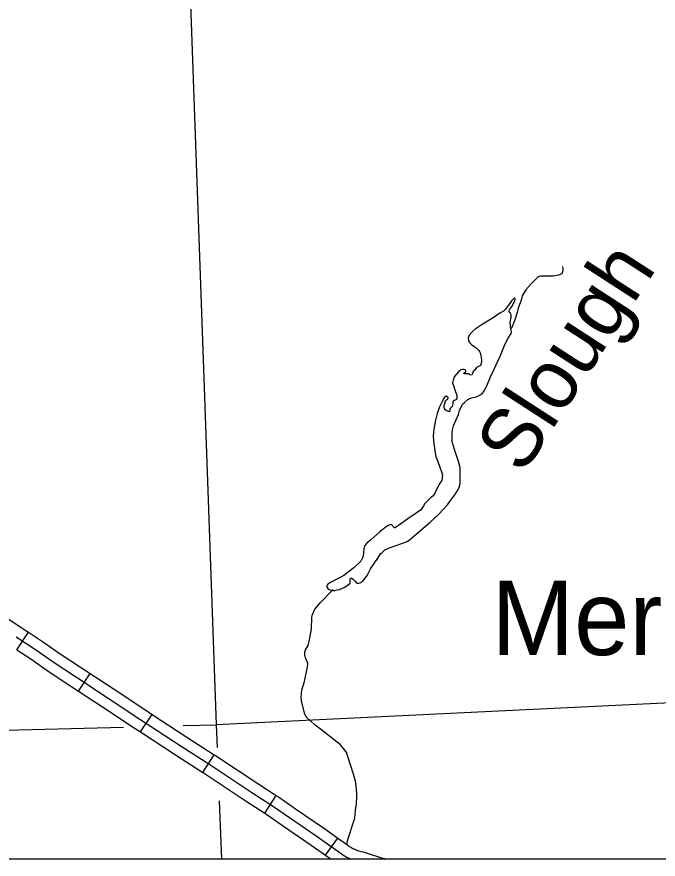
# Model space of a CAD drawing. Extents: x 1720274 to 1751788, y 372074 to 391887.
# Drawn here: x 1734994 to 1735715, y 374371 to 375317 of the extents above; entities that cross this region are included whole.
import ezdxf

# ---------------------------------------------------------------- set-up
doc = ezdxf.new("R2010")
doc.units = 0
for name, color, linetype in [('Level 25', 7, 'Continuous'), ('Level 32', 7, 'Continuous'), ('Level 35', 7, 'Continuous'), ('Level 5', 7, 'Continuous'), ('R_Draft', 7, 'Continuous')]:
    doc.layers.add(name, color=color, linetype=linetype)

msp = doc.modelspace()

# ---------------------------------------------------------------- linework, layer by layer
at = {"layer": 'Level 32'}
for p, q in [((1734993.93, 374606.46), (1735006.85, 374626.33)), ((1735063.16, 374560.09), (1735076.22, 374579.87)), ((1735132.84, 374514.16), (1735145.85, 374533.97)), ((1735202.92, 374468.64), (1735215.69, 374488.61)), ((1735272.54, 374422.84), (1735285.46, 374442.71)), ((1735340.78, 374375.71), (1735354.51, 374395.03))]:
    msp.add_line(p, q, dxfattribs=at)
for points in [[(1734937.32, 374672.25), (1734999.77, 374630.93), (1735006.85, 374626.33)], [(1735006.85, 374626.33), (1735022.85, 374615.93), (1735041.32, 374602.75), (1735066.53, 374586.27), (1735076.22, 374579.87)], [(1734993.27, 374621.02), (1735016.17, 374606.14), (1735034.63, 374592.96), (1735060.02, 374576.37), (1735096.69, 374552.16), (1735133.44, 374527.95), (1735178.48, 374498.35), (1735210.7, 374477.73), (1735258.14, 374446.33), (1735281.3, 374431.28), (1735300.45, 374418.1), (1735331.56, 374396.8), (1735358.44, 374377.71), (1735359.91, 374376.64), (1735361.42, 374375.61), (1735362.96, 374374.64), (1735364.53, 374373.73), (1735366.14, 374372.86), (1735367.77, 374372.06), (1735369.4, 374371.32)], [(1734993.93, 374606.46), (1735009.5, 374596.34), (1735027.95, 374583.18), (1735053.51, 374566.46), (1735063.16, 374560.09)], [(1735076.22, 374579.87), (1735103.21, 374562.05), (1735139.95, 374537.84), (1735145.85, 374533.97)], [(1735063.16, 374560.09), (1735090.16, 374542.26), (1735126.93, 374518.05), (1735132.84, 374514.16)], [(1735145.85, 374533.97), (1735184.93, 374508.29), (1735215.69, 374488.61)], [(1735132.84, 374514.16), (1735172.03, 374488.4), (1735202.92, 374468.64)], [(1735215.69, 374488.6), (1735217.17, 374487.66), (1735264.64, 374456.24), (1735285.46, 374442.71)], [(1735202.92, 374468.64), (1735204.24, 374467.8), (1735251.64, 374436.42), (1735272.54, 374422.84)], [(1735285.46, 374442.71), (1735287.89, 374441.13), (1735307.16, 374427.87), (1735338.34, 374406.52), (1735354.51, 374395.03)], [(1735272.54, 374422.84), (1735274.71, 374421.43), (1735293.74, 374408.33), (1735324.78, 374387.08), (1735340.78, 374375.71)], [(1735354.51, 374395.03), (1735365.36, 374387.33), (1735366.73, 374386.33), (1735367.9, 374385.53), (1735369.1, 374384.78), (1735370.32, 374384.07), (1735371.56, 374383.4), (1735372.83, 374382.77), (1735374.12, 374382.19), (1735375.42, 374381.66), (1735376.75, 374381.17), (1735378.09, 374380.72), (1735379.45, 374380.32), (1735380.81, 374379.97), (1735382.91, 374379.51), (1735404.81, 374372.58), (1735406.93, 374371.88), (1735408.47, 374371.32)], [(1735340.78, 374375.71), (1735346.96, 374371.32)]]:
    msp.add_lwpolyline(points, dxfattribs=at)
at = {"layer": 'Level 35'}
for points in [[(1735607.12, 375036.81), (1735607.45, 375033.83), (1735607.45, 375032.17), (1735607.12, 375031.02), (1735606.79, 375029.86), (1735606.13, 375028.87), (1735605.14, 375028.21), (1735602.66, 375027.38), (1735596.72, 375026.06), (1735594.07, 375025.89), (1735589.12, 375026.06), (1735586.47, 375026.22), (1735584.65, 375026.22), (1735582.42, 375026.01), (1735581.3, 375025.74), (1735580.25, 375025.22), (1735578.93, 375024.43), (1735578.08, 375023.7), (1735571.49, 375017.18), (1735565.97, 375010.59), (1735562.68, 375005.85), (1735561.82, 375003.87), (1735560.57, 374999.13), (1735557.35, 374990.04), (1735556.03, 374985.23), (1735553.2, 374976.01), (1735549.65, 374967.64), (1735548.97, 374966.88)], [(1735551.51, 375000.38), (1735550.11, 374998.77), (1735546.99, 374994.46), (1735542.94, 374989.01), (1735540.73, 374986.81), (1735536.68, 374984.6), (1735529.14, 374979.27), (1735516.97, 374971.96), (1735508.74, 374966.51), (1735505.38, 374963.49), (1735502.6, 374960.13), (1735501.26, 374957.56), (1735501.21, 374956.69), (1735501.16, 374955.88), (1735501.32, 374954.52), (1735501.59, 374953.49), (1735502.46, 374951.76), (1735505.27, 374948.89), (1735509.98, 374945.63), (1735512.04, 374943.68), (1735513.02, 374942.6), (1735513.78, 374941.46), (1735514.43, 374940.1), (1735515.4, 374936.47), (1735515.89, 374932.08), (1735515.89, 374929.75), (1735515.83, 374928.61), (1735515.45, 374926.77), (1735514.75, 374925.68), (1735511.88, 374924.38), (1735510.31, 374923.46), (1735509.5, 374922.48), (1735508.31, 374920.69), (1735507.6, 374920.15), (1735506.63, 374919.12), (1735506.14, 374917.82), (1735505.92, 374916.63), (1735505.65, 374915.82), (1735505.11, 374915.27), (1735504.35, 374915.06), (1735503.43, 374915.17), (1735502.56, 374915.92), (1735501.86, 374916.3), (1735501.1, 374916.52), (1735499.96, 374916.47), (1735499.31, 374916.41), (1735498.12, 374916.41), (1735497.2, 374916.47), (1735496.44, 374916.74), (1735496.33, 374917.17), (1735496.61, 374917.71), (1735497.42, 374917.98), (1735498.45, 374918.53), (1735498.61, 374919.12), (1735498.61, 374919.56), (1735498.18, 374920.32), (1735497.58, 374920.8), (1735495.68, 374921.24), (1735494.44, 374921.24), (1735492.92, 374920.8), (1735490.05, 374918.69), (1735485.39, 374912.94), (1735484.04, 374909.09), (1735483.71, 374907.79), (1735483.61, 374906.06), (1735484.47, 374903.46), (1735486.21, 374898.58), (1735486.86, 374896.3), (1735487.61, 374894.13), (1735488.16, 374892.07), (1735488.26, 374890.01), (1735488.26, 374888.6), (1735487.78, 374887.58), (1735487.23, 374887.09), (1735486.62, 374886.91), (1735485.77, 374886.61), (1735484.8, 374886.31), (1735483.95, 374885.21), (1735483.71, 374882.66), (1735482.92, 374879.86), (1735481.52, 374878.22), (1735480.8, 374877.37), (1735480.49, 374876.16), (1735480.49, 374875.37), (1735480.49, 374874.64), (1735480.25, 374874.27), (1735479.7, 374874.03), (1735478.85, 374874.09), (1735477.64, 374874.52), (1735476.12, 374875.67), (1735474.54, 374876.89), (1735474.3, 374877.56), (1735474.12, 374878.35), (1735474.12, 374879.2), (1735474.18, 374880.47), (1735474.36, 374882.17), (1735475.15, 374884.18), (1735475.39, 374885.58), (1735475.94, 374886.49), (1735476.73, 374887.22), (1735477.7, 374887.95)], [(1735549.8, 374963.52), (1735549.78, 374963.91), (1735549.37, 374965.45), (1735548.97, 374966.88), (1735548.36, 374974.21), (1735549.23, 374979.89), (1735549.3, 374982.45), (1735548.93, 374983.81), (1735548.62, 374984.42), (1735548.19, 374984.79), (1735547.63, 374985.29), (1735547.33, 374985.72), (1735547.14, 374986.15), (1735547.08, 374986.83), (1735547.14, 374987.63), (1735547.94, 374989.17), (1735549.97, 374992), (1735552.62, 374996.81), (1735553.67, 374998.66), (1735553.85, 374999.95), (1735553.85, 375000.51), (1735553.79, 375001), (1735553.54, 375001.18), (1735553.24, 375001.37), (1735552.93, 375001.37), (1735552.56, 375001.25), (1735551.51, 375000.38)], [(1735372.72, 374698.32), (1735361.34, 374689.73), (1735358.13, 374688.03), (1735354.17, 374686.14), (1735346.26, 374681.99), (1735344.66, 374680.78), (1735343.4, 374680.1), (1735342.72, 374679.13), (1735342.43, 374678.54), (1735342.43, 374677.57), (1735342.53, 374676.5), (1735343.4, 374675.33), (1735344.96, 374674.07), (1735346.7, 374673.29), (1735348.06, 374673.2), (1735349.33, 374673.2), (1735351.27, 374673.2), (1735353.99, 374673.78), (1735356.42, 374674.26), (1735362.54, 374676.69), (1735368.27, 374680.88), (1735368.46, 374681.36), (1735368.46, 374682.53), (1735368.46, 374683.5), (1735368.46, 374684.76), (1735368.46, 374685.64), (1735368.56, 374686.32), (1735368.95, 374686.71), (1735369.43, 374686.81), (1735370.21, 374686.81), (1735372.15, 374685.44), (1735373.03, 374684.57), (1735374.58, 374683.01), (1735375.36, 374682.04), (1735376.33, 374681.26), (1735377.1, 374681.07), (1735378.27, 374681.17), (1735379.53, 374681.75), (1735382.35, 374683.31), (1735384.68, 374685.93), (1735387.4, 374689.72), (1735391.38, 374697.3), (1735399.44, 374709.36), (1735402.65, 374714.12), (1735404.4, 374715.87), (1735406.15, 374717.62), (1735407.6, 374718.69), (1735408.57, 374719.28), (1735411.39, 374720.44), (1735424.31, 374725.11), (1735432.47, 374728.03), (1735435.19, 374729.77), (1735437.81, 374732.21), (1735445, 374738.23), (1735458.5, 374749.8), (1735467.87, 374758.56), (1735477.7, 374769.15), (1735481.35, 374774.12), (1735486.04, 374780.59), (1735489.78, 374786.49), (1735490.91, 374789.02), (1735491.94, 374793.15), (1735492.12, 374798.4), (1735492.12, 374804.77), (1735491.94, 374810.77), (1735491.75, 374812.65), (1735490.34, 374817.99), (1735485.57, 374831.39), (1735483.41, 374838.89), (1735483.04, 374840.67), (1735482.95, 374844.89), (1735482.95, 374850.14), (1735483.51, 374853.42), (1735484.63, 374858.11), (1735485.57, 374860.74), (1735490.16, 374870.86), (1735491.47, 374875.08), (1735494.77, 374882.21), (1735496.56, 374884), (1735500.73, 374887.5), (1735503.11, 374888.77), (1735505.12, 374889.59), (1735508.47, 374890.19), (1735510.03, 374890.56), (1735511.97, 374891.38), (1735515.32, 374893.32), (1735517.11, 374894.66), (1735518.3, 374896.15), (1735519.19, 374897.34), (1735522.17, 374903.01), (1735526.27, 374913.07), (1735529.54, 374920.22), (1735537.21, 374936.99), (1735542.58, 374949.96), (1735545.95, 374956.41), (1735549.19, 374961.84), (1735549.76, 374963.12), (1735549.82, 374963.3), (1735549.8, 374963.52)], [(1735477.7, 374887.95), (1735478.43, 374888.67), (1735478.49, 374889.34), (1735478.43, 374889.65), (1735478, 374890.32), (1735477.28, 374890.8), (1735476.73, 374891.04), (1735476.18, 374891.17), (1735475.58, 374891.11), (1735475.09, 374890.86), (1735474.48, 374890.25), (1735473.39, 374888.31), (1735469.02, 374879.26), (1735466.11, 374871.97), (1735464.27, 374864.28), (1735462.38, 374854.16), (1735461.81, 374846.69), (1735462.1, 374841.02), (1735463.42, 374829.95), (1735464.74, 374823.52), (1735468.52, 374813.97), (1735471.83, 374804.04), (1735472.21, 374802.34), (1735472.02, 374800.92), (1735471.83, 374798.65), (1735471.36, 374797.05), (1735469.47, 374793.83), (1735465.78, 374787.21), (1735463.42, 374782.2), (1735461.62, 374779.36), (1735458.6, 374777), (1735453.97, 374772.27), (1735451.89, 374770.38), (1735451.14, 374768.58), (1735449.06, 374765.18), (1735447.64, 374763.38), (1735442.63, 374759.88), (1735433.28, 374753.45), (1735422.7, 374745.98), (1735420.53, 374744.37), (1735418.54, 374743.43), (1735417.79, 374743.52), (1735417.12, 374744.28), (1735416.75, 374744.94), (1735416.27, 374745.79), (1735415.33, 374746.74), (1735414.48, 374746.93), (1735413.06, 374746.83), (1735410.98, 374746.08), (1735407.58, 374743.43), (1735401.72, 374738.89), (1735391.71, 374730), (1735387.27, 374726.03), (1735384.72, 374723.29), (1735383.68, 374719.41), (1735383.21, 374712.13), (1735382.45, 374709.67), (1735380.28, 374706.17), (1735372.72, 374698.32)], [(1735365.92, 374393.44), (1735373.57, 374417.36), (1735374.3, 374426.35), (1735375.51, 374433.4), (1735376, 374440.94), (1735376, 374445.56), (1735375.03, 374453.58), (1735374.3, 374458.93), (1735372.11, 374466.95), (1735368.96, 374477.4), (1735364.34, 374491.01), (1735361.43, 374495.39), (1735357.3, 374500.01), (1735347.1, 374508.03), (1735335.2, 374517.27), (1735329.12, 374521.64), (1735319.41, 374530.88), (1735317.71, 374534.28), (1735313.82, 374548.63), (1735313.58, 374553.73), (1735314.07, 374561.27), (1735317.22, 374570.99), (1735320.14, 374585.58), (1735320.96, 374589.8), (1735320.83, 374591.22), (1735319.94, 374593.92), (1735318.52, 374596.62), (1735317.75, 374598.29), (1735317.37, 374600.34), (1735317.37, 374603.81), (1735318.4, 374606.38), (1735321.35, 374611.39), (1735322.76, 374617.82), (1735325.07, 374630.16), (1735325.46, 374643.14), (1735325.97, 374645.96), (1735328.92, 374652.26), (1735335.6, 374660.1), (1735339.45, 374664.21), (1735348.95, 374674.11)], [(1735364.87, 374388.09), (1735365.92, 374393.44)]]:
    msp.add_lwpolyline(points, dxfattribs=at)
at = {"layer": 'Level 5'}
for points in [[(1735187.9, 375363.92), (1735217.8, 374522.36)], [(1735984.16, 374559.26), (1735217.8, 374522.36)], [(1734612.56, 374507), (1735113.74, 374519.72)], [(1735180.77, 374521.42), (1735217.8, 374522.36)], [(1735217.8, 374522.36), (1735218.84, 374496.76)], [(1735221.27, 374436.85), (1735223.93, 374371.32)]]:
    msp.add_lwpolyline(points, dxfattribs=at)
at = {"layer": 'R_Draft'}
msp.add_lwpolyline([(1729990.7, 381816.11), (1741847.55, 381816.11), (1741847.55, 374371.32), (1729990.7, 374371.32)], close=True, dxfattribs=at)

# ---------------------------------------------------------------- texts
at = {"layer": 'Level 25'}
msp.add_text('Merck', height=83.424, dxfattribs=at).set_placement((1735527.26, 374600.54))
at = {"layer": 'Level 35'}
msp.add_text('Slough', height=66.739, rotation=57.08989, dxfattribs=at).set_placement((1735562.36, 374801.78))

doc.saveas('drawing.dxf')
